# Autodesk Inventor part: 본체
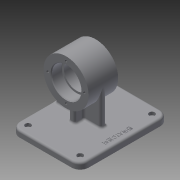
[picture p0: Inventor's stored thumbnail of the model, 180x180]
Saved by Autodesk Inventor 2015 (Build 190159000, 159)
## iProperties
Created: 2019-09
Part Number: 본체
Material: 일반
Document SubType Name: Modeling
Designer: now
Density: 1 g/cm^3
Appearance: 기본값
Author: now
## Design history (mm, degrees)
sketch "스케치1"
  geometry: C1 r 32 at (0, 0); 1 further point
  constraints: 1 centre point, 1 coincident
  dimensions: "d0" = 64 diameter of C1
extrude "돌출1" new body sketch "스케치1" stored distance "d1" = 42; taper "d2" = 0 deg
sketch "스케치2"
  geometry: L1 (32, 0)-(-32, 0); L2 (-32, 0)-(-32, -59); L3 (-32, -59)-(32, -59); L4 (32, -59)-(32, 0); 2 further points
  constraints: 8 end point, 2 parallel, 1 horizontal, 1 horizontal alignment, 1 midpoint, 1 perpendicular, 1 other
  dimensions: "d3" = 64 distance of L1.start L1.end; "d4" = 59 distance of L1.end L2.end
extrude "돌출2" join sketch "스케치2" stored distance "d5" = 8; taper "d6" = 0 deg
sketch "스케치3"
  geometry: L1 (-21, -32)-(-21, 32) reference; L2 (-21, 32)-(21, 32) reference; L3 (21, 32)-(21, -32) reference; L4 (21, -32)-(4, -32) reference; L5 (4, -32)-(4, -59) reference; L6 (4, -59)-(-4, -59) reference; L7 (-4, -59)-(-4, -32) reference; L8 (-4, -32)-(-21, -32) reference; L9 (-17, 0)-(17, 0); L10 (17, 0)-(17, -59); L11 (17, -59)-(-17, -59); L12 (-17, -59)-(-17, 0); 2 further points
  constraints: 8 end point, 2 parallel, 1 coincident, 1 horizontal, 1 midpoint, 1 perpendicular
  dimensions: "d7" = 59 distance of L9.end L10.end; "d8" = 34 distance of L9.start L9.end
extrude "돌출3" join sketch "스케치3" distance "d9" = 8; taper "d10" = 0 deg
sketch "스케치4"
  geometry: C1 r 32 at (0, 0) reference; C2 r 21 at (0, 0)
  constraints: 1 centre point, 1 coincident
  dimensions: "d11" = 42 diameter of C2
extrude "돌출4" cut sketch "스케치4" distance "d12" = 15; taper "d13" = 0 deg
sketch "스케치5"
  geometry: C1 r 21 at (0, 0) reference; C2 r 18 at (0, 0)
  constraints: 1 centre point, 1 coincident
  dimensions: "d14" = 36 diameter of C2
extrude "돌출5" cut sketch "스케치5" stored distance "d15" = 15; taper "d16" = 0 deg
node "작업 평면1"
sketch "스케치6"
  geometry: L1 (62, -63)-(-36, -63); L2 (-36, -63)-(-36, 63); L3 (-36, 63)-(62, 63); L4 (62, 63)-(62, -63); 1 further point
  constraints: 8 end point, 2 parallel, 1 horizontal, 1 perpendicular
  dimensions: "d18" = 62 distance from line of point (0, 0) L4; "d19" = 98 distance between parallel lines of L2 L4; "d20" = 126 distance of L3.end L1.start; "d21" = 63 distance from line of point (0, 0) L3
extrude "돌출6" join sketch "스케치6" distance "d22" = 9; taper "d23" = 0 deg
sketch "스케치7"
  geometry: C1 r 21 at (0, 0) reference; 1 further point
  constraints: 1 vertical alignment
  dimensions: "d24" = 26 distance of C1.centre point (0, -26)
hole "구멍1" sketch "스케치7" at (0, -26) diameter "d25" = 3.242; stored, may be unused: countersink angle "d29" = 90 deg, drill point angle "d31" = 118 deg; dims "d26" = 8, "d27" = 4, "d28" = 2, "d30" = 10
fillet "모깎기1" dims "d35" = 12
sketch "스케치8"
  geometry: A1 r 12 centre (50, -51) between (50, -63) and (62, -51) reference; A2 r 12 centre (50, 51) between (62, 51) and (50, 63) reference; A3 r 12 centre (-24, 51) between (-24, 63) and (-36, 51) reference; A4 r 12 centre (-24, -51) between (-36, -51) and (-24, -63) reference; 1 further point
hole "구멍2" sketch "스케치8" at (50, -51), (50, 51), (-24, -51), (-24, 51) diameter "d36" = 4.5; stored, may be unused: countersink angle "d40" = 90 deg, drill point angle "d42" = 118 deg; dims "d37" = 8, "d38" = 8, "d39" = 4.4, "d41" = 10
chamfer "모따기1" distance "d43" = 1; stored, may be unused: second distance "d44" = 2, angle "d45" = 45 deg
fillet "모깎기2" dims "d46" = 0.3
fillet "모깎기3" dims "d47" = 3
fillet "모깎기4" dims "d48" = 3
fillet "모깎기5" dims "d49" = 3
sketch "스케치9"
  geometry: L1 (62, -51)-(62, 51) reference; L2 (-24, -63)-(50, -63) reference; 2 further points
  constraints: 1 other
  dimensions: "d50" = 10 distance from line of point (52, 0) L1; "d51" = 63 distance from line of point (52, 0) L2
feature "엠보싱1" sketch "스케치9" dims "d52" = 0.5, "d53" = 0
node "솔리드1"
mirror "대칭1"
pattern_circular "원형 패턴1" dims angle "d33" = 360 deg
mirror "대칭2"
node "절단 모서리 투영1"
node "절단 모서리 투영2"
other parameters: "d17" = -59
